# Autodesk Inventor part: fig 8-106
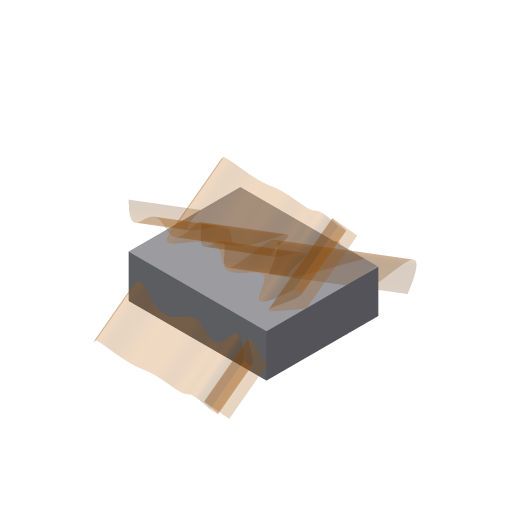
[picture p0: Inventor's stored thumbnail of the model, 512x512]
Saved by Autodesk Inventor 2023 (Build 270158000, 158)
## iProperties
Part Number: fig 8-106
Document SubType Name: Modeling
Created: 2002-12
Designer: deepak
Density: 1 g/cm^3
Material: Generic
Appearance: Default
Control State: 0
Master: False
Checked Out: False
Shininess: 64.0
Length Units: 11269
Angle Units: 11279
Time Units: 11290
Mass Units: 11283
Length Display Precision: 3
Angle Display Precision: 2
Compacted: True
Density: 0.0
Volumn: 0.0
Area: 0.0
PropertySet Name: Model Information
Author: deepak
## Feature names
1. Extrusion1
## Parameters: d1 = 0, d2 = 0, d3 = 0, d4 = 0, d5 = 0
